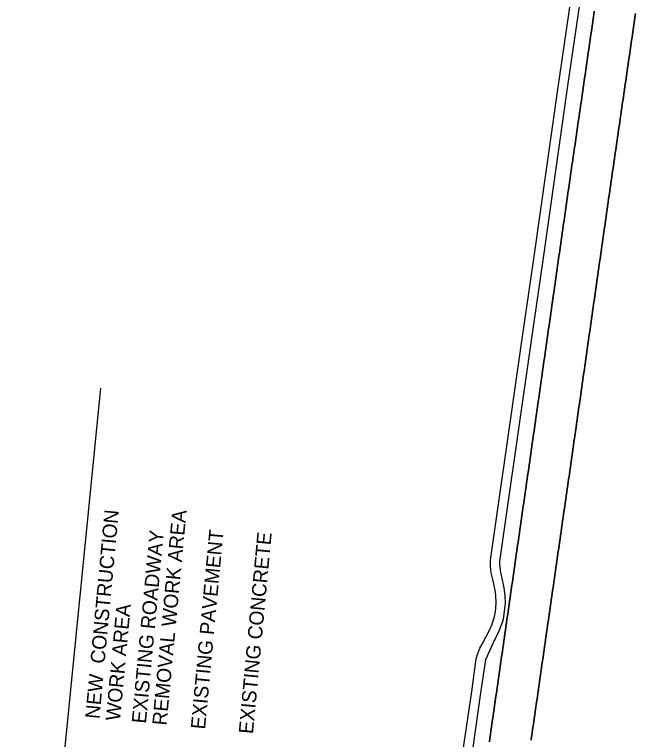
# Model space of a CAD drawing. Extents: x 1795987 to 1799689, y 243690 to 251545.
# Drawn here: x 1797261.4 to 1797598.9, y 247453.1 to 247847.5 of the extents above; entities that cross this region are included whole.
import ezdxf

# ---------------------------------------------------------------- set-up
doc = ezdxf.new("R2010")
doc.units = 0
for name, color, linetype in [('EP', 7, 'Continuous'), ('LEGEND', 7, 'Continuous'), ('Level 62', 7, 'Continuous')]:
    doc.layers.add(name, color=color, linetype=linetype)

msp = doc.modelspace()

# ---------------------------------------------------------------- linework, layer by layer
at = {"layer": 'EP'}
for points in [[(1797502.98, 247431.42), (1797509.89, 247479.28), (1797512.41, 247496.92), (1797513.21, 247499.92), (1797514.39, 247502.79), (1797515.55, 247504.9), (1797517.77, 247509.13), (1797519.86, 247513.31), (1797520.78, 247515.42), (1797521.93, 247518.67), (1797522.28, 247519.96), (1797522.83, 247522.6), (1797523.1, 247524.61), (1797523.26, 247527.63), (1797523.1, 247531.02), (1797522.82, 247533.27), (1797521.91, 247537.81), (1797521.35, 247540.15), (1797520.54, 247543.7), (1797520.12, 247547.31), (1797520.09, 247550.71), (1797523.74, 247576.05), (1797530.2, 247621.54), (1797536.99, 247668.47), (1797543.83, 247715.8), (1797550.42, 247761.89), (1797557, 247808), (1797563.79, 247855.1)], [(1797568.69, 247854.47), (1797561.87, 247807.43), (1797555.34, 247761.13), (1797548.75, 247715.15), (1797541.84, 247667.67), (1797535.11, 247620.83), (1797528.62, 247575.39), (1797524.96, 247549.93), (1797525.06, 247548.02), (1797525.55, 247543.91), (1797526.45, 247539.86), (1797526.65, 247538.96), (1797527.41, 247535.59), (1797527.98, 247531.38), (1797528.16, 247527.13), (1797526.97, 247518.48), (1797526.28, 247516.25), (1797524.64, 247511.95), (1797522.63, 247507.8), (1797522.17, 247506.93), (1797521.53, 247505.59), (1797517.43, 247496.48), (1797514.72, 247478.52), (1797507.92, 247430.67)]]:
    msp.add_lwpolyline(points, dxfattribs=at)
at = {"layer": 'LEGEND'}
msp.add_line((1797261.35, 247170.53), (1797308.29, 247644.28), dxfattribs=at)
at = {"layer": 'Level 62'}
for points in [[(1797519.54, 247451.89), (1797519.82, 247453.87), (1797520.1, 247455.84), (1797520.38, 247457.81), (1797520.66, 247459.79), (1797520.94, 247461.76), (1797521.23, 247463.73), (1797521.51, 247465.7), (1797521.79, 247467.68), (1797522.07, 247469.65), (1797522.35, 247471.62), (1797522.63, 247473.59), (1797522.91, 247475.55), (1797523.2, 247477.5), (1797523.48, 247479.45), (1797523.76, 247481.4), (1797524.04, 247483.36), (1797524.32, 247485.31), (1797524.6, 247487.26), (1797524.88, 247489.21), (1797525.16, 247491.17), (1797525.44, 247493.12), (1797525.72, 247495.07), (1797526, 247497.02), (1797526.28, 247498.98), (1797526.56, 247500.93), (1797526.85, 247502.88), (1797527.13, 247504.83), (1797527.41, 247506.79), (1797527.69, 247508.74), (1797527.97, 247510.69), (1797528.25, 247512.64), (1797528.53, 247514.6), (1797528.81, 247516.55), (1797529.09, 247518.5), (1797529.37, 247520.45), (1797529.65, 247522.41), (1797529.93, 247524.36), (1797530.21, 247526.31), (1797530.49, 247528.26), (1797530.78, 247530.22), (1797531.06, 247532.17), (1797531.34, 247534.12), (1797531.62, 247536.07), (1797531.9, 247538.03), (1797532.18, 247539.98), (1797532.46, 247541.93), (1797532.74, 247543.88), (1797533.02, 247545.84), (1797533.3, 247547.79), (1797533.58, 247549.74), (1797533.86, 247551.7), (1797534.14, 247553.65), (1797534.42, 247555.6), (1797534.71, 247557.55), (1797534.99, 247559.51), (1797535.27, 247561.46), (1797535.55, 247563.41), (1797535.83, 247565.36), (1797536.11, 247567.32), (1797536.39, 247569.27), (1797536.67, 247571.22), (1797536.95, 247573.17), (1797537.23, 247575.13), (1797537.51, 247577.08), (1797537.79, 247579.03), (1797538.07, 247580.98), (1797538.35, 247582.94), (1797538.64, 247584.89), (1797538.92, 247586.84), (1797539.2, 247588.79), (1797539.48, 247590.75), (1797539.76, 247592.7), (1797540.04, 247594.65), (1797540.32, 247596.6), (1797540.6, 247598.56), (1797540.88, 247600.51), (1797541.16, 247602.46), (1797541.44, 247604.41), (1797541.72, 247606.37), (1797542, 247608.32), (1797542.29, 247610.27), (1797542.57, 247612.24), (1797542.85, 247614.22), (1797543.13, 247616.19), (1797543.41, 247618.17), (1797543.69, 247620.14), (1797543.97, 247622.11), (1797544.25, 247624.09), (1797544.53, 247626.06), (1797544.81, 247628.04), (1797545.1, 247630.01), (1797545.38, 247631.98), (1797545.66, 247633.96), (1797545.94, 247635.93), (1797546.22, 247637.9), (1797546.5, 247639.88), (1797546.78, 247641.85), (1797547.06, 247643.83), (1797547.34, 247645.8), (1797547.63, 247647.77), (1797547.91, 247649.75), (1797548.19, 247651.72), (1797548.47, 247653.7), (1797548.75, 247655.67), (1797549.03, 247657.64), (1797549.31, 247659.62), (1797549.59, 247661.59), (1797549.87, 247663.57), (1797550.16, 247665.54), (1797550.44, 247667.51), (1797550.72, 247669.49), (1797551, 247671.46), (1797551.28, 247673.43), (1797551.56, 247675.41), (1797551.84, 247677.38), (1797552.12, 247679.36), (1797552.4, 247681.33), (1797552.69, 247683.3), (1797552.97, 247685.28), (1797553.25, 247687.25), (1797553.53, 247689.23), (1797553.81, 247691.2), (1797554.09, 247693.17), (1797554.37, 247695.15), (1797554.65, 247697.12), (1797554.93, 247699.09), (1797555.22, 247701.07), (1797555.5, 247703.04), (1797555.78, 247705.02), (1797556.06, 247706.99), (1797556.34, 247708.96), (1797556.62, 247710.94), (1797556.9, 247712.91), (1797557.18, 247714.89), (1797557.46, 247716.86), (1797557.75, 247718.83), (1797558.03, 247720.81), (1797558.31, 247722.78), (1797558.59, 247724.75), (1797558.87, 247726.73), (1797559.15, 247728.7), (1797559.43, 247730.68), (1797559.71, 247732.65), (1797559.99, 247734.62), (1797560.28, 247736.6), (1797560.56, 247738.57), (1797560.84, 247740.55), (1797561.12, 247742.52), (1797561.4, 247744.49), (1797561.68, 247746.47), (1797561.96, 247748.44), (1797562.24, 247750.41), (1797562.52, 247752.39), (1797562.81, 247754.37), (1797563.1, 247756.35), (1797563.38, 247758.32), (1797563.67, 247760.3), (1797563.96, 247762.28), (1797564.24, 247764.26), (1797564.53, 247766.24), (1797564.82, 247768.22), (1797565.1, 247770.2), (1797565.39, 247772.18), (1797565.68, 247774.15), (1797565.96, 247776.13), (1797566.25, 247778.11), (1797566.54, 247780.09), (1797566.82, 247782.07), (1797567.11, 247784.05), (1797567.4, 247786.03), (1797567.68, 247788), (1797567.97, 247789.98), (1797568.26, 247791.96), (1797568.54, 247793.94), (1797568.83, 247795.92), (1797569.12, 247797.9), (1797569.4, 247799.88), (1797569.69, 247801.85), (1797569.98, 247803.83), (1797570.26, 247805.81), (1797570.55, 247807.79), (1797570.84, 247809.77), (1797571.12, 247811.75), (1797571.41, 247813.73), (1797571.7, 247815.71), (1797571.98, 247817.68), (1797572.27, 247819.66), (1797572.56, 247821.64), (1797572.84, 247823.62), (1797573.13, 247825.6), (1797573.42, 247827.58), (1797573.7, 247829.56), (1797573.99, 247831.53), (1797574.28, 247833.51), (1797574.56, 247835.49), (1797574.85, 247837.47), (1797575.13, 247839.45), (1797575.42, 247841.43), (1797575.71, 247843.41), (1797575.99, 247845.38), (1797576.28, 247847.36), (1797576.57, 247849.34)], [(1797576.57, 247849.34), (1797576.28, 247847.36), (1797575.99, 247845.38), (1797575.71, 247843.41), (1797575.42, 247841.43), (1797575.13, 247839.45), (1797574.85, 247837.47), (1797574.56, 247835.49), (1797574.28, 247833.51), (1797573.99, 247831.53), (1797573.7, 247829.56), (1797573.42, 247827.58), (1797573.13, 247825.6), (1797572.84, 247823.62), (1797572.56, 247821.64), (1797572.27, 247819.66), (1797571.98, 247817.68), (1797571.7, 247815.71), (1797571.41, 247813.73), (1797571.12, 247811.75), (1797570.84, 247809.77), (1797570.55, 247807.79), (1797570.26, 247805.81), (1797569.98, 247803.83), (1797569.69, 247801.85), (1797569.4, 247799.88), (1797569.12, 247797.9), (1797568.83, 247795.92), (1797568.54, 247793.94), (1797568.26, 247791.96), (1797567.97, 247789.98), (1797567.68, 247788), (1797567.4, 247786.03), (1797567.11, 247784.05), (1797566.82, 247782.07), (1797566.54, 247780.09), (1797566.25, 247778.11), (1797565.96, 247776.13), (1797565.68, 247774.15), (1797565.39, 247772.18), (1797565.1, 247770.2), (1797564.82, 247768.22), (1797564.53, 247766.24), (1797564.24, 247764.26), (1797563.96, 247762.28), (1797563.67, 247760.3), (1797563.38, 247758.32), (1797563.1, 247756.35), (1797562.81, 247754.37), (1797562.52, 247752.39), (1797562.24, 247750.41), (1797561.96, 247748.44), (1797561.68, 247746.47), (1797561.4, 247744.49), (1797561.12, 247742.52), (1797560.84, 247740.55), (1797560.56, 247738.57), (1797560.28, 247736.6), (1797559.99, 247734.62), (1797559.71, 247732.65), (1797559.43, 247730.68), (1797559.15, 247728.7), (1797558.87, 247726.73), (1797558.59, 247724.75), (1797558.31, 247722.78), (1797558.03, 247720.81), (1797557.75, 247718.83), (1797557.46, 247716.86), (1797557.18, 247714.89), (1797556.9, 247712.91), (1797556.62, 247710.94), (1797556.34, 247708.96), (1797556.06, 247706.99), (1797555.78, 247705.02), (1797555.5, 247703.04), (1797555.22, 247701.07), (1797554.93, 247699.09), (1797554.65, 247697.12), (1797554.37, 247695.15), (1797554.09, 247693.17), (1797553.81, 247691.2), (1797553.53, 247689.23), (1797553.25, 247687.25), (1797552.97, 247685.28), (1797552.69, 247683.3), (1797552.4, 247681.33), (1797552.12, 247679.36), (1797551.84, 247677.38), (1797551.56, 247675.41), (1797551.28, 247673.43), (1797551, 247671.46), (1797550.72, 247669.49), (1797550.44, 247667.51), (1797550.16, 247665.54), (1797549.87, 247663.57), (1797549.59, 247661.59), (1797549.31, 247659.62), (1797549.03, 247657.64), (1797548.75, 247655.67), (1797548.47, 247653.7), (1797548.19, 247651.72), (1797547.91, 247649.75), (1797547.63, 247647.77), (1797547.34, 247645.8), (1797547.06, 247643.83), (1797546.78, 247641.85), (1797546.5, 247639.88), (1797546.22, 247637.9), (1797545.94, 247635.93), (1797545.66, 247633.96), (1797545.38, 247631.98), (1797545.1, 247630.01), (1797544.81, 247628.04), (1797544.53, 247626.06), (1797544.25, 247624.09), (1797543.97, 247622.11), (1797543.69, 247620.14), (1797543.41, 247618.17), (1797543.13, 247616.19), (1797542.85, 247614.22), (1797542.57, 247612.24), (1797542.29, 247610.27), (1797542, 247608.32), (1797541.72, 247606.37), (1797541.44, 247604.41), (1797541.16, 247602.46), (1797540.88, 247600.51), (1797540.6, 247598.56), (1797540.32, 247596.6), (1797540.04, 247594.65), (1797539.76, 247592.7), (1797539.48, 247590.75), (1797539.2, 247588.79), (1797538.92, 247586.84), (1797538.64, 247584.89), (1797538.35, 247582.94), (1797538.07, 247580.98), (1797537.79, 247579.03), (1797537.51, 247577.08), (1797537.23, 247575.13), (1797536.95, 247573.17), (1797536.67, 247571.22), (1797536.39, 247569.27), (1797536.11, 247567.32), (1797535.83, 247565.36), (1797535.55, 247563.41), (1797535.27, 247561.46), (1797534.99, 247559.51), (1797534.71, 247557.55), (1797534.42, 247555.6), (1797534.14, 247553.65), (1797533.86, 247551.7), (1797533.58, 247549.74), (1797533.3, 247547.79), (1797533.02, 247545.84), (1797532.74, 247543.88), (1797532.46, 247541.93), (1797532.18, 247539.98), (1797531.9, 247538.03), (1797531.62, 247536.07), (1797531.34, 247534.12), (1797531.06, 247532.17), (1797530.78, 247530.22), (1797530.49, 247528.26), (1797530.21, 247526.31), (1797529.93, 247524.36), (1797529.65, 247522.41), (1797529.37, 247520.45), (1797529.09, 247518.5), (1797528.81, 247516.55), (1797528.53, 247514.6), (1797528.25, 247512.64), (1797527.97, 247510.69), (1797527.69, 247508.74), (1797527.41, 247506.79), (1797527.13, 247504.83), (1797526.85, 247502.88), (1797526.56, 247500.93), (1797526.28, 247498.98), (1797526, 247497.02), (1797525.72, 247495.07), (1797525.44, 247493.12), (1797525.16, 247491.17), (1797524.88, 247489.21), (1797524.6, 247487.26), (1797524.32, 247485.31), (1797524.04, 247483.36), (1797523.76, 247481.4), (1797523.48, 247479.45), (1797523.2, 247477.5), (1797522.91, 247475.55), (1797522.63, 247473.59), (1797522.35, 247471.62), (1797522.07, 247469.65), (1797521.79, 247467.68), (1797521.51, 247465.7), (1797521.23, 247463.73), (1797520.94, 247461.76), (1797520.66, 247459.79), (1797520.38, 247457.81), (1797520.1, 247455.84), (1797519.82, 247453.87), (1797519.54, 247451.89)], [(1797598.95, 247848.09), (1797598.67, 247846.11), (1797598.38, 247844.13), (1797598.09, 247842.16), (1797597.81, 247840.18), (1797597.52, 247838.2), (1797597.24, 247836.22), (1797596.95, 247834.25), (1797596.66, 247832.27), (1797596.38, 247830.29), (1797596.09, 247828.31), (1797595.8, 247826.34), (1797595.52, 247824.36), (1797595.23, 247822.38), (1797594.94, 247820.4), (1797594.66, 247818.43), (1797594.37, 247816.45), (1797594.08, 247814.47), (1797593.8, 247812.49), (1797593.51, 247810.52), (1797593.23, 247808.54), (1797592.94, 247806.56), (1797592.65, 247804.58), (1797592.37, 247802.61), (1797592.08, 247800.63), (1797591.79, 247798.65), (1797591.51, 247796.67), (1797591.22, 247794.7), (1797590.93, 247792.72), (1797590.65, 247790.74), (1797590.36, 247788.76), (1797590.07, 247786.79), (1797589.79, 247784.81), (1797589.5, 247782.83), (1797589.22, 247780.85), (1797588.93, 247778.88), (1797588.64, 247776.9), (1797588.36, 247774.92), (1797588.07, 247772.94), (1797587.78, 247770.97), (1797587.5, 247768.99), (1797587.21, 247767.01), (1797586.92, 247765.03), (1797586.64, 247763.06), (1797586.35, 247761.08), (1797586.06, 247759.1), (1797585.78, 247757.12), (1797585.49, 247755.15), (1797585.21, 247753.17), (1797584.92, 247751.19), (1797584.63, 247749.21), (1797584.35, 247747.24), (1797584.07, 247745.27), (1797583.79, 247743.29), (1797583.51, 247741.32), (1797583.23, 247739.34), (1797582.95, 247737.37), (1797582.67, 247735.4), (1797582.38, 247733.42), (1797582.1, 247731.45), (1797581.82, 247729.48), (1797581.54, 247727.5), (1797581.26, 247725.53), (1797580.98, 247723.56), (1797580.7, 247721.58), (1797580.42, 247719.61), (1797580.14, 247717.63), (1797579.85, 247715.66), (1797579.57, 247713.69), (1797579.29, 247711.71), (1797579.01, 247709.74), (1797578.73, 247707.77), (1797578.45, 247705.79), (1797578.17, 247703.82), (1797577.89, 247701.84), (1797577.61, 247699.87), (1797577.32, 247697.9), (1797577.04, 247695.92), (1797576.76, 247693.95), (1797576.48, 247691.98), (1797576.2, 247690), (1797575.92, 247688.03), (1797575.64, 247686.06), (1797575.36, 247684.08), (1797575.08, 247682.11), (1797574.79, 247680.13), (1797574.51, 247678.16), (1797574.23, 247676.19), (1797573.95, 247674.21), (1797573.67, 247672.24), (1797573.39, 247670.27), (1797573.11, 247668.29), (1797572.83, 247666.32), (1797572.55, 247664.34), (1797572.26, 247662.37), (1797571.98, 247660.4), (1797571.7, 247658.42), (1797571.42, 247656.45), (1797571.14, 247654.48), (1797570.86, 247652.5), (1797570.58, 247650.53), (1797570.3, 247648.55), (1797570.02, 247646.58), (1797569.74, 247644.61), (1797569.45, 247642.63), (1797569.17, 247640.66), (1797568.89, 247638.69), (1797568.61, 247636.71), (1797568.33, 247634.74), (1797568.05, 247632.77), (1797567.77, 247630.79), (1797567.49, 247628.82), (1797567.21, 247626.84), (1797566.92, 247624.87), (1797566.64, 247622.9), (1797566.36, 247620.92), (1797566.08, 247618.95), (1797565.8, 247616.98), (1797565.52, 247615), (1797565.24, 247613.03), (1797564.96, 247611.05), (1797564.68, 247609.08), (1797564.39, 247607.11), (1797564.11, 247605.15), (1797563.83, 247603.2), (1797563.55, 247601.25), (1797563.27, 247599.3), (1797562.99, 247597.34), (1797562.71, 247595.39), (1797562.43, 247593.44), (1797562.15, 247591.49), (1797561.87, 247589.53), (1797561.59, 247587.58), (1797561.31, 247585.63), (1797561.03, 247583.68), (1797560.75, 247581.72), (1797560.46, 247579.77), (1797560.18, 247577.82), (1797559.9, 247575.87), (1797559.62, 247573.91), (1797559.34, 247571.96), (1797559.06, 247570.01), (1797558.78, 247568.06), (1797558.5, 247566.1), (1797558.22, 247564.15), (1797557.94, 247562.2), (1797557.66, 247560.25), (1797557.38, 247558.29), (1797557.1, 247556.34), (1797556.81, 247554.39), (1797556.53, 247552.43), (1797556.25, 247550.48), (1797555.97, 247548.53), (1797555.69, 247546.58), (1797555.41, 247544.62), (1797555.13, 247542.67), (1797554.85, 247540.72), (1797554.57, 247538.77), (1797554.29, 247536.81), (1797554.01, 247534.86), (1797553.73, 247532.91), (1797553.45, 247530.96), (1797553.17, 247529), (1797552.88, 247527.05), (1797552.6, 247525.1), (1797552.32, 247523.15), (1797552.04, 247521.19), (1797551.76, 247519.24), (1797551.48, 247517.29), (1797551.2, 247515.34), (1797550.92, 247513.38), (1797550.64, 247511.43), (1797550.36, 247509.48), (1797550.08, 247507.53), (1797549.8, 247505.57), (1797549.52, 247503.62), (1797549.23, 247501.67), (1797548.95, 247499.72), (1797548.67, 247497.76), (1797548.39, 247495.81), (1797548.11, 247493.86), (1797547.83, 247491.91), (1797547.55, 247489.95), (1797547.27, 247488), (1797546.99, 247486.05), (1797546.71, 247484.09), (1797546.43, 247482.14), (1797546.15, 247480.19), (1797545.87, 247478.24), (1797545.59, 247476.28), (1797545.3, 247474.33), (1797545.02, 247472.38), (1797544.74, 247470.43), (1797544.46, 247468.45), (1797544.18, 247466.48), (1797543.9, 247464.51), (1797543.62, 247462.54), (1797543.34, 247460.56), (1797543.05, 247458.59), (1797542.77, 247456.62), (1797542.49, 247454.65), (1797542.21, 247452.67)], [(1797542.21, 247452.67), (1797542.49, 247454.65), (1797542.77, 247456.62), (1797543.05, 247458.59), (1797543.34, 247460.56), (1797543.62, 247462.54), (1797543.9, 247464.51), (1797544.18, 247466.48), (1797544.46, 247468.45), (1797544.74, 247470.43), (1797545.02, 247472.38), (1797545.3, 247474.33), (1797545.59, 247476.28), (1797545.87, 247478.24), (1797546.15, 247480.19), (1797546.43, 247482.14), (1797546.71, 247484.09), (1797546.99, 247486.05), (1797547.27, 247488), (1797547.55, 247489.95), (1797547.83, 247491.91), (1797548.11, 247493.86), (1797548.39, 247495.81), (1797548.67, 247497.76), (1797548.95, 247499.72), (1797549.23, 247501.67), (1797549.52, 247503.62), (1797549.8, 247505.57), (1797550.08, 247507.53), (1797550.36, 247509.48), (1797550.64, 247511.43), (1797550.92, 247513.38), (1797551.2, 247515.34), (1797551.48, 247517.29), (1797551.76, 247519.24), (1797552.04, 247521.19), (1797552.32, 247523.15), (1797552.6, 247525.1), (1797552.88, 247527.05), (1797553.17, 247529), (1797553.45, 247530.96), (1797553.73, 247532.91), (1797554.01, 247534.86), (1797554.29, 247536.81), (1797554.57, 247538.77), (1797554.85, 247540.72), (1797555.13, 247542.67), (1797555.41, 247544.62), (1797555.69, 247546.58), (1797555.97, 247548.53), (1797556.25, 247550.48), (1797556.53, 247552.43), (1797556.81, 247554.39), (1797557.1, 247556.34), (1797557.38, 247558.29), (1797557.66, 247560.25), (1797557.94, 247562.2), (1797558.22, 247564.15), (1797558.5, 247566.1), (1797558.78, 247568.06), (1797559.06, 247570.01), (1797559.34, 247571.96), (1797559.62, 247573.91), (1797559.9, 247575.87), (1797560.18, 247577.82), (1797560.46, 247579.77), (1797560.75, 247581.72), (1797561.03, 247583.68), (1797561.31, 247585.63), (1797561.59, 247587.58), (1797561.87, 247589.53), (1797562.15, 247591.49), (1797562.43, 247593.44), (1797562.71, 247595.39), (1797562.99, 247597.34), (1797563.27, 247599.3), (1797563.55, 247601.25), (1797563.83, 247603.2), (1797564.11, 247605.15), (1797564.39, 247607.11), (1797564.68, 247609.08), (1797564.96, 247611.05), (1797565.24, 247613.03), (1797565.52, 247615), (1797565.8, 247616.98), (1797566.08, 247618.95), (1797566.36, 247620.92), (1797566.64, 247622.9), (1797566.92, 247624.87), (1797567.21, 247626.84), (1797567.49, 247628.82), (1797567.77, 247630.79), (1797568.05, 247632.77), (1797568.33, 247634.74), (1797568.61, 247636.71), (1797568.89, 247638.69), (1797569.17, 247640.66), (1797569.45, 247642.63), (1797569.74, 247644.61), (1797570.02, 247646.58), (1797570.3, 247648.55), (1797570.58, 247650.53), (1797570.86, 247652.5), (1797571.14, 247654.48), (1797571.42, 247656.45), (1797571.7, 247658.42), (1797571.98, 247660.4), (1797572.26, 247662.37), (1797572.55, 247664.34), (1797572.83, 247666.32), (1797573.11, 247668.29), (1797573.39, 247670.27), (1797573.67, 247672.24), (1797573.95, 247674.21), (1797574.23, 247676.19), (1797574.51, 247678.16), (1797574.79, 247680.13), (1797575.08, 247682.11), (1797575.36, 247684.08), (1797575.64, 247686.06), (1797575.92, 247688.03), (1797576.2, 247690), (1797576.48, 247691.98), (1797576.76, 247693.95), (1797577.04, 247695.92), (1797577.32, 247697.9), (1797577.61, 247699.87), (1797577.89, 247701.84), (1797578.17, 247703.82), (1797578.45, 247705.79), (1797578.73, 247707.77), (1797579.01, 247709.74), (1797579.29, 247711.71), (1797579.57, 247713.69), (1797579.85, 247715.66), (1797580.14, 247717.63), (1797580.42, 247719.61), (1797580.7, 247721.58), (1797580.98, 247723.56), (1797581.26, 247725.53), (1797581.54, 247727.5), (1797581.82, 247729.48), (1797582.1, 247731.45), (1797582.38, 247733.42), (1797582.67, 247735.4), (1797582.95, 247737.37), (1797583.23, 247739.34), (1797583.51, 247741.32), (1797583.79, 247743.29), (1797584.07, 247745.27), (1797584.35, 247747.24), (1797584.63, 247749.21), (1797584.92, 247751.19), (1797585.21, 247753.17), (1797585.49, 247755.15), (1797585.78, 247757.12), (1797586.06, 247759.1), (1797586.35, 247761.08), (1797586.64, 247763.06), (1797586.92, 247765.03), (1797587.21, 247767.01), (1797587.5, 247768.99), (1797587.78, 247770.97), (1797588.07, 247772.94), (1797588.36, 247774.92), (1797588.64, 247776.9), (1797588.93, 247778.88), (1797589.22, 247780.85), (1797589.5, 247782.83), (1797589.79, 247784.81), (1797590.07, 247786.79), (1797590.36, 247788.76), (1797590.65, 247790.74), (1797590.93, 247792.72), (1797591.22, 247794.7), (1797591.51, 247796.67), (1797591.79, 247798.65), (1797592.08, 247800.63), (1797592.37, 247802.61), (1797592.65, 247804.58), (1797592.94, 247806.56), (1797593.23, 247808.54), (1797593.51, 247810.52), (1797593.8, 247812.49), (1797594.08, 247814.47), (1797594.37, 247816.45), (1797594.66, 247818.43), (1797594.94, 247820.4), (1797595.23, 247822.38), (1797595.52, 247824.36), (1797595.8, 247826.34), (1797596.09, 247828.31), (1797596.38, 247830.29), (1797596.66, 247832.27), (1797596.95, 247834.25), (1797597.24, 247836.22), (1797597.52, 247838.2), (1797597.81, 247840.18), (1797598.09, 247842.16), (1797598.38, 247844.13), (1797598.67, 247846.11), (1797598.95, 247848.09)]]:
    msp.add_lwpolyline(points, dxfattribs=at)

# ---------------------------------------------------------------- texts
at = {"layer": 'LEGEND'}
for s, height, p in [('NEW  CONSTRUCTION', 7.7999, (1797307.5, 247464.07)), ('REMOVAL WORK AREA', 7.7999, (1797343.98, 247460.51)), ('EXISTING ROADWAY', 7.7999, (1797332.79, 247461.56)), ('EXISTING PAVEMENT', 7.7999, (1797364.92, 247458.39)), ('EXISTING CONCRETE', 7.7999, (1797390.96, 247455.89)), ('WORK AREA', 7.8, (1797318.69, 247463.02))]:
    msp.add_text(s, height=height, rotation=84.6544, dxfattribs=at).set_placement(p)

doc.saveas('drawing.dxf')
